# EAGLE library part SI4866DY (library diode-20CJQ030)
Vishay Siliconix's Si4866DY N-Channel Reduced Qg, Fast Switching MOSFET FEATURES: TrenchFET Power MOSFETS PWM Optimized for High Efficiency Low Output Voltage 100% RG Tested APPLICATIONS Synchronous Rectifier Point-of-Load Synchronous Buck Converter Please send any comments to: messi@users.sourceforge.net
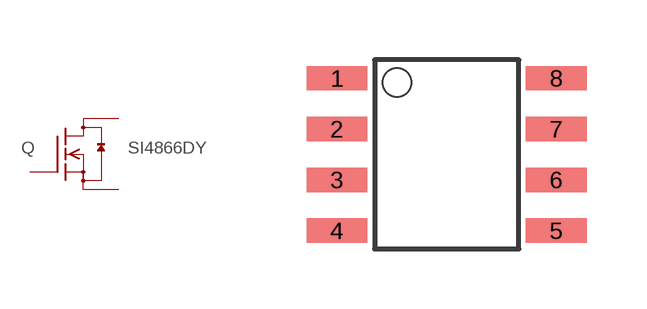
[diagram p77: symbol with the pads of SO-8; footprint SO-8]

Designator prefix Q

## SI4866DY  [SO-8]
1  S  pas
2  S  pas
3  S  pas
4  G  pas
5  D  pas
6  D  pas
7  D  pas
8  D  pas

## Footprint SO-8 (pad centres in mm)
small outline
smd 1.524 x 0.61: 1 -2.743,1.27; 2 -2.743,0; 3 -2.743,-1.27; 4 -2.743,-2.54; 5 2.743,-2.54; 6 2.743,-1.27; 7 2.743,0; 8 2.743,1.27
